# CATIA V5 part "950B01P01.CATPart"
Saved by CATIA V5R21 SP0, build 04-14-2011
Part number: 950B01P01
Bounding box of the stored display mesh (mm): x -33.4 to 33.4, y -127 to 127, z -8 to 9
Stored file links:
  C:\Users\ALI OZGUN\Desktop\alhan\950B01P01.CATPart
  C:\Users\ALI OZGUN\Desktop\alhan\943B01P01.CATPart
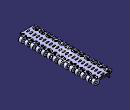
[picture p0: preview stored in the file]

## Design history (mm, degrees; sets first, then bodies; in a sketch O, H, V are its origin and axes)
Body1 (main body)
Body2
  Sketch1 on zx-plane, origin (0, 0, 0), H (-1, 0, 0), V (0, 0, 1)
    construction line L1 (25.4, 8) -> (25.4, -8)
    line L2 (25.4, -8) -> (-25.4, -8)
    construction line L3 (-25.4, -8) -> (-25.4, 8)
    line L4 (-25.4, 8) -> (25.4, 8)
    point P3 (-25.4, -8)
    arc A1 centre (25.4, 0) radius 8 from (25.4, 8) to (25.4, -8) cw
    arc A2 centre (-25.4, 0) radius 8 from (-25.4, 8) to (-25.4, -8) ccw
    point P7 (-25.4, -8)
    length L4 = 50.8
    length L3 = 16
    vertical: L1 V, L3 V
    horizontal: L2 H, L4 H
    equidistance: L1 L3 O, L2 L4 O
    tangency: A1 L2, A2 L4, A2 L2, L4 A1
    coincidence: P7 L2, P3 P7
  Pad1: profile Sketch1, direction (0, 1, 0), length 127, mirrored extent
  Body3
    Sketch2 on face of Pad1 from Sketch1.L4, origin (0, 0, 8), H (1, 0, 0), V (0, 1, 0)
      line L1 (19.4, 118) -> (45.1506, 118)
      line L2 (45.1506, 118) -> (45.1506, 108.9)
      line L3 (45.1506, 108.9) -> (19.4, 108.9)
      line L4 (19.4, 108.9) -> (19.4, 118)
      reference projected line E1 (-25.4, 127) -> (25.4, 127) from edge [face of Pad1 from Sketch1.L4 | end face of Pad1]
      reference projected line E2 through (25.4, 0) direction (0, 1) from axis of face of Pad1 from Sketch1.A2
      distance L1 E1 = 9
      distance E2 L4 = 6
      distance L3 L1 = 9.1
      horizontal: L1 H, L3 H
      vertical: L2 V, L4 V
    Pad2: profile Sketch2, direction (0, 0, -1), length 18, mirrored extent
    RectPattern1: of Pad2, direction 1 instances 15, spacing 18.1, along axis of face of Pad1 from Sketch1.A2 reversed
  Remove1: tool Body3
  Body4
    Solid1: linked copy from another document
    Symmetry1: Reference yz-plane, ToTransfor Solid1
    Translate1: Direction edge [face of Pad1 from Sketch1.A2 | face of Pad1 from Sketch1.L4], Length 9.05, ToTransfor Symmetry1
  Remove2: tool Body4
  Sketch3 on zx-plane, origin (0, 0, 0), H (-1, 0, 0), V (0, 0, 1)
    circle A1 centre (25.4, 0) radius 3.15
    circle A2 centre (-25.4, 0) radius 3.15
    reference projected arc E1 centre (25.4, 0) radius 8 from (25.4, -8) to (25.4, 8) ccw from edge [face of Pad1 from Sketch1.A1 | face of Solid1]
    reference projected arc E2 centre (-25.4, 0) radius 8 from (-25.4, 8) to (-25.4, -8) ccw from edge [face of Pad1 from Sketch1.A2 | end face of Pad1]
    radius A1 = 3.15
    radius A2 = 3.15
    concentricity: A1 E1, A2 E2
  Pocket1: profile Sketch3, direction (0, -1, 0), length 204, mirrored extent
  Body5
    Sketch4 on face of Pad1 from Sketch1.L4, origin (0, 0, 8), H (1, 0, 0), V (0, 1, 0)
      axis line L1 (-18.8181, 122.2) -> (20.8616, 122.2)
      reference projected line E1 (-25.4, 127) -> (25.4, 127) from edge [face of Pad1 from Sketch1.L4 | end face of Pad1]
      arc A1 centre (0.4, 116.2) radius 8 from (-4.8915, 122.2) to (5.6915, 122.2) cw
      point P4 (-4.8915, 122.2)
      point P5 (5.6915, 122.2)
      arc A2 centre (0.4, 128.2) radius 8 from (-4.8915, 122.2) to (5.6915, 122.2) ccw
      point P6 (0.4, 128.2)
      point P7 (-4.8915, 122.2)
      reference projected line E2 through (25.4, 0) direction (0, 1) from axis of face of Pad1
      point P8 (10.2784, 122.2)
      arc A3 centre (22.9541, 117.7288) radius 8 from (15.1781, 119.6086) to (23.8472, 125.6788) cw
      arc A4 centre (16.0712, 127.5586) radius 8 from (15.1781, 119.6086) to (23.8472, 125.6788) ccw
      point P14 (-18.1996, 123.9721)
      arc A5 centre (-13.4199, 127.4191) radius 8 from (-13.2231, 119.4216) to (-19.4, 122.1052) cw
      arc A6 centre (-21.1333, 118.2266) radius 8 from (-13.2231, 119.4216) to (-19.4, 126.0366) ccw
      projected line E3 (-19.4, 127) -> (-19.4, 117.95) from edge [face of Solid1 | face of Pad1 from Sketch1.L4]
      projected line E4 (-19.4, 126.0366) -> (-19.4, 122.1052) from edge [face of Solid1 | face of Pad1 from Sketch1.L4]
      distance L1 E1 = 4.8
      radius A1 = 8
      radius A2 = 8
      distance P6 E2 = 25
      distance A1 A2 = 4
      horizontal: L1 H
      coincidence: P4 L1, P5 L1, P7 A1, P7 L1
    Pad3: profile Sketch4, direction (0, 0, 1), length 1
    Sketch5 on face of Pad1 from Sketch1.L4, origin (0, 0, 8), H (1, 0, 0), V (0, 1, 0)
      axis line L1 (-31.102, 113.15) -> (46.1463, 113.15)
      reference projected line E1 (-19.4, 117.95) -> (-25.4, 117.95) from edge [face of Solid1 | face of Pad1 from Sketch1.L4]
      arc A1 centre (0.8036, 105.9125) radius 7.9999 from (6.0951, 111.9124) to (-4.4879, 111.9124) ccw
      arc A2 centre (0.8036, 117.9123) radius 7.9999 from (-4.4879, 111.9124) to (6.0951, 111.9124) ccw
      arc A3 centre (15.2167, 106.6639) radius 7.9999 from (19.4, 113.4829) to (14.3235, 114.6138) ccw
      arc A4 centre (22.0995, 116.4936) radius 7.9999 from (14.3235, 114.6138) to (19.4, 108.9629) ccw
      arc A5 centre (-13.9367, 107.099) radius 7.9999 from (-13.0435, 115.049) to (-21.7126, 108.9788) ccw
      arc A6 centre (-20.8195, 116.9287) radius 7.9999 from (-21.7126, 108.9788) to (-13.0435, 115.049) ccw
      projected line E2 (19.4, 118) -> (19.4, 108.9) from edge [face of Pad1 from Sketch1.L4 | face of Pad2 from Sketch2.L4]
      projected line E3 (19.4, 113.4829) -> (19.4, 108.9629) from edge [face of Pad1 from Sketch1.L4 | face of Pad2 from Sketch2.L4]
      distance L1 E1 = 4.8
    Pad4: profile Sketch5, direction (0, 0, 1), length 1
    RectPattern2: of the body so far, direction 1 instances 13, spacing 21, along edge [face of Solid1 | face of Pad1 from Sketch1.L4]
    Sketch6 on face of Pad1 from Sketch1.L4, origin (0, 0, 8), H (1, 0, 0), V (0, 1, 0)
      line L1 (35.409, -143.7774) -> (-39.1047, -143.7774)
      line L2 (-39.1047, -143.7774) -> (-39.1047, -125.5844)
      line L3 (-39.1047, -125.5844) -> (35.409, -125.5844)
      line L4 (35.409, -125.5844) -> (35.409, -143.7774)
      horizontal: L1 H, L3 H
      vertical: L2 V, L4 V
    Pocket2: profile Sketch6, direction (0, 0, -1), length 1, mirrored extent
  Assemble1: tool Body5
  Body6
    Solid2: solid without history
  Remove3: tool Body6
  Body7
    Solid3: solid without history
  Remove4: tool Body7
  Body8
    Solid4: solid without history
  Remove5: tool Body8
  RemoveFace1: RemoveFaces (face of Solid3; face of Pocket1 from Sketch3.A2; face of Pad1 from Sketch1.A2; face of Solid3; face of Solid3)
  Body9
    Solid5: solid without history
  Remove6: tool Body9
  Sketch7 on zx-plane, origin (0, 0, 0), H (-1, 0, 0), V (0, 0, 1)
    line L1 (0, 72) -> (0, 6.9718)
    point P1 (0, 72)
    reference projected line E1 (-25.4, -8) -> (25.4, -8) from edge [face of Pad1 from Sketch1.L2 | end face of Pad1]
    distance P1 E1 = 80
    coincidence: P1 V
    vertical: L1 V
